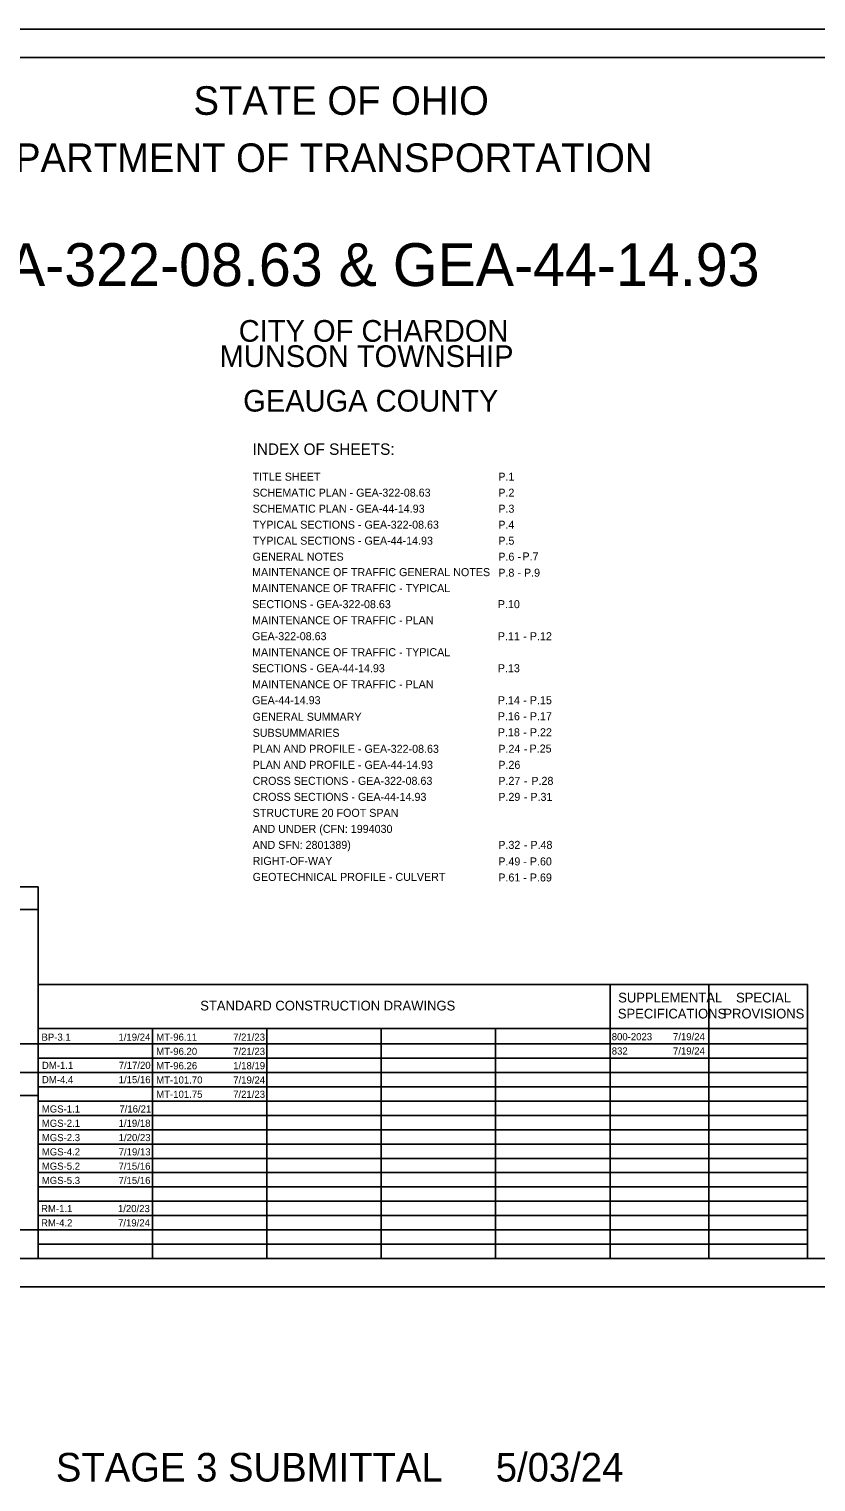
# Model space of a CAD drawing. Extents: x -6.1 to 38, y -7.7 to 22.
# Drawn here: x 11.09 to 24.85, y -3.41 to 22 of the extents above; entities that cross this region are included whole.
import ezdxf

# ---------------------------------------------------------------- set-up
doc = ezdxf.new("R2010")
doc.units = 0
for name, color, linetype in [('Default', 7, 'Continuous'), ('SH_Border', 7, 'Continuous'), ('SH_Cut_Line', 7, 'Continuous'), ('SH_Data', 7, 'Continuous'), ('SH_Text', 7, 'Continuous')]:
    doc.layers.add(name, color=color, linetype=linetype)

msp = doc.modelspace()

# ---------------------------------------------------------------- linework, layer by layer
at = {"layer": 'SH_Border'}
msp.add_lwpolyline([(1.5, 21.5), (33.5, 21.5), (33.5, 0.5), (1.5, 0.5)], close=True, dxfattribs=at)
at = {"layer": 'SH_Cut_Line'}
msp.add_lwpolyline([(0, 0), (34, 0), (34, 22), (0, 22)], close=True, dxfattribs=at)
at = {"layer": 'SH_Data'}
for p, q in [((8.45, 7), (11.25, 7)), ((11.25, 7), (11.25, 3.75)), ((8.45, 6.6), (11.25, 6.6)), ((11.25, 5.292), (24.7, 5.292)), ((11.25, 0.5), (11.25, 5.292)), ((11.25, 0.5), (11.25, 5.292)), ((21.25, 0.5), (21.25, 5.292)), ((22.975, 0.5), (22.975, 5.292)), ((24.7, 0.5), (24.7, 5.292)), ((11.25, 4.521), (24.7, 4.521)), ((13.25, 0.5), (13.25, 4.521)), ((15.25, 0.5), (15.25, 4.521)), ((17.25, 0.5), (17.25, 4.521)), ((19.25, 0.5), (19.25, 4.521)), ((11.25, 4.25), (24.7, 4.25)), ((11.25, 4), (24.7, 4)), ((8.45, 3.75), (11.25, 3.75)), ((8.45, 3.75), (11.25, 3.75)), ((8.45, 3.75), (11.25, 3.75)), ((11.25, 3.75), (24.7, 3.75)), ((11.25, 3.75), (11.25, 0.5)), ((8.45, 3.35), (11.25, 3.35)), ((11.25, 3.5), (24.7, 3.5)), ((11.25, 3.25), (24.7, 3.25)), ((11.25, 3), (24.7, 3)), ((11.25, 2.75), (24.7, 2.75)), ((11.25, 2.5), (24.7, 2.5)), ((11.25, 2.25), (24.7, 2.25)), ((11.25, 2), (24.7, 2)), ((11.25, 1.75), (24.7, 1.75)), ((11.25, 1.5), (24.7, 1.5)), ((11.25, 1.25), (24.7, 1.25)), ((11.25, 1), (24.7, 1)), ((11.25, 0.75), (24.7, 0.75)), ((8.45, 0.5), (11.25, 0.5))]:
    msp.add_line(p, q, dxfattribs=at)
for points in [[(8.45, 3.75), (8.45, 4.25), (11.25, 4.25), (11.25, 3.75)], [(8.45, 0.5), (8.45, 1), (11.25, 1), (11.25, 0.5)]]:
    msp.add_lwpolyline(points, close=True, dxfattribs=at)

# ---------------------------------------------------------------- texts
at = {"layer": 'Default'}
for s, p in [('BP-3.1', (11.31, 4.307)), ('1/19/24', (12.656, 4.307)), ('MT-96.11', (13.317, 4.308)), ('7/21/23', (14.661, 4.308)), ('800-2023', (21.28, 4.315)), ('7/19/24', (22.351, 4.315)), ('MT-96.20', (13.317, 4.058)), ('7/21/23', (14.661, 4.058)), ('832', (21.28, 4.065)), ('7/19/24', (22.351, 4.065)), ('DM-1.1', (11.318, 3.814)), ('7/17/20', (12.661, 3.814)), ('MT-96.26', (13.317, 3.808)), ('1/18/19', (14.662, 3.808)), ('DM-4.4', (11.318, 3.564)), ('1/15/16', (12.66, 3.564)), ('MT-101.70', (13.317, 3.558)), ('7/19/24', (14.663, 3.558)), ('MT-101.75', (13.317, 3.308)), ('7/21/23', (14.661, 3.308)), ('MGS-1.1', (11.316, 3.051)), ('7/16/21', (12.672, 3.051)), ('MGS-2.1', (11.316, 2.801)), ('1/19/18', (12.659, 2.801)), ('MGS-2.3', (11.316, 2.551)), ('1/20/23', (12.66, 2.551)), ('MGS-4.2', (11.316, 2.301)), ('7/19/13', (12.66, 2.301)), ('MGS-5.2', (11.316, 2.051)), ('7/15/16', (12.658, 2.051)), ('MGS-5.3', (11.316, 1.801)), ('7/15/16', (12.658, 1.801)), ('RM-1.1', (11.303, 1.309)), ('1/20/23', (12.647, 1.309)), ('RM-4.2', (11.303, 1.059)), ('7/19/24', (12.649, 1.059))]:
    msp.add_text(s, height=0.125, dxfattribs=at).set_placement(p)
at = {"layer": 'SH_Text'}
for s, height, p in [('STATE OF OHIO', 0.5, (13.968, 20.5)), ('DEPARTMENT OF TRANSPORTATION', 0.5, (9.92, 19.5)), ('GEA-322-08.63 & GEA-44-14.93', 0.75, (9.258, 17.505)), ('CITY OF CHARDON', 0.38, (14.759, 16.531)), ('MUNSON TOWNSHIP', 0.38, (14.425, 16.089)), ('GEAUGA COUNTY', 0.38, (14.837, 15.31)), ('INDEX OF SHEETS:', 0.2, (15.002, 14.553)), ('TITLE SHEET', 0.14, (15.002, 14.102)), ('P.1', 0.14, (19.297, 14.102)), ('SCHEMATIC PLAN - GEA-322-08.63', 0.14, (15.002, 13.822)), ('P.2', 0.14, (19.297, 13.822)), ('SCHEMATIC PLAN - GEA-44-14.93', 0.14, (15.002, 13.542)), ('P.3', 0.14, (19.297, 13.542)), ('TYPICAL SECTIONS - GEA-322-08.63', 0.14, (15.002, 13.262)), ('P.4', 0.14, (19.297, 13.262)), ('TYPICAL SECTIONS - GEA-44-14.93', 0.14, (15.002, 12.982)), ('P.5', 0.14, (19.297, 12.982)), ('GENERAL NOTES', 0.14, (15.002, 12.702)), ('P.6', 0.14, (19.297, 12.702)), (' - ', 0.14, (19.579, 12.702)), ('P.7', 0.14, (19.719, 12.707)), ('MAINTENANCE OF TRAFFIC GENERAL NOTES', 0.14, (14.993, 12.432)), ('P.8', 0.14, (19.297, 12.422)), (' - ', 0.14, (19.579, 12.422)), ('P.9', 0.14, (19.746, 12.422)), ('MAINTENANCE OF TRAFFIC - TYPICAL', 0.14, (14.993, 12.152)), ('SECTIONS - GEA-322-08.63', 0.14, (14.993, 11.872)), ('P.10', 0.14, (19.289, 11.872)), ('MAINTENANCE OF TRAFFIC - PLAN', 0.14, (14.993, 11.592)), ('GEA-322-08.63', 0.14, (14.993, 11.312)), ('P.11', 0.14, (19.289, 11.312)), ('P.12', 0.14, (19.849, 11.312)), (' - ', 0.14, (19.682, 11.312)), ('MAINTENANCE OF TRAFFIC - TYPICAL', 0.14, (14.993, 11.032)), ('SECTIONS - GEA-44-14.93', 0.14, (14.993, 10.752)), ('P.13', 0.14, (19.289, 10.752)), ('MAINTENANCE OF TRAFFIC - PLAN', 0.14, (14.993, 10.472)), ('GEA-44-14.93', 0.14, (14.993, 10.192)), ('P.14', 0.14, (19.289, 10.192)), (' - ', 0.14, (19.682, 10.192)), ('P.15', 0.14, (19.849, 10.192)), ('GENERAL SUMMARY', 0.14, (15.002, 9.902)), ('P.16', 0.14, (19.289, 9.912)), (' - ', 0.14, (19.682, 9.912)), ('P.17', 0.14, (19.849, 9.912)), ('SUBSUMMARIES', 0.14, (15.002, 9.622)), ('P.18', 0.14, (19.289, 9.632)), (' - ', 0.14, (19.682, 9.632)), ('P.22', 0.14, (19.849, 9.632)), ('PLAN AND PROFILE - GEA-322-08.63', 0.14, (15.002, 9.342)), ('P.24', 0.14, (19.297, 9.342)), (' -', 0.14, (19.691, 9.342)), ('P.25', 0.14, (19.844, 9.347)), ('PLAN AND PROFILE - GEA-44-14.93', 0.14, (15.002, 9.062)), ('P.26', 0.14, (19.297, 9.062)), ('CROSS SECTIONS - GEA-322-08.63', 0.14, (15.002, 8.782)), ('P.27', 0.14, (19.297, 8.782)), ('P.28', 0.14, (19.875, 8.782)), ('CROSS SECTIONS - GEA-44-14.93', 0.14, (15.002, 8.502)), ('P.29', 0.14, (19.297, 8.502)), (' - ', 0.14, (19.691, 8.782)), ('P.31', 0.14, (19.858, 8.502)), (' - ', 0.14, (19.691, 8.502)), ('STRUCTURE 20 FOOT SPAN', 0.14, (15.002, 8.222)), ('AND UNDER (CFN: 1994030', 0.14, (15.002, 7.942)), ('AND SFN: 2801389)', 0.14, (15.002, 7.662)), ('P.32', 0.14, (19.297, 7.662)), (' - ', 0.14, (19.691, 7.662)), ('P.48', 0.14, (19.858, 7.662)), ('RIGHT-OF-WAY', 0.14, (15.002, 7.382)), ('P.49 - P.60', 0.14, (19.297, 7.373)), ('GEOTECHNICAL PROFILE - CULVERT', 0.14, (15.002, 7.102)), ('P.61 - P.69', 0.14, (19.297, 7.092)), ('SUPPLEMENTAL', 0.17, (21.393, 4.976)), ('SPECIAL', 0.17, (23.454, 4.976)), ('STANDARD CONSTRUCTION DRAWINGS', 0.17, (14.086, 4.836)), ('SPECIFICATIONS', 0.17, (21.387, 4.696)), ('PROVISIONS', 0.17, (23.232, 4.696)), ('STAGE 3 SUBMITTAL     5/03/24', 0.5, (11.562, -3.402))]:
    msp.add_text(s, height=height, dxfattribs=at).set_placement(p)

doc.saveas('drawing.dxf')
